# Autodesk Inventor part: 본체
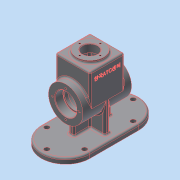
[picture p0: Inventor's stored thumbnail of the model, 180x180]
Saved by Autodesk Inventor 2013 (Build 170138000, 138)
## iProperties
Created: 2019-01
Part Number: 본체
Material: 알루미늄 6061
Document SubType Name: Modeling
Designer: mduedu
Density: 2.71 g/cm^3
Mass: 1057.72 g
Surface Area: 916.19 cm^2
Volume: 390.304 cm^3
Author: mduedu
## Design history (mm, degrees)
sketch "스케치1"
  geometry: C1 r 32 at (0, 0); 1 further point
  constraints: 1 centre point, 1 coincident
  dimensions: "d0" = 64 diameter of C1
extrude "돌출1" new body sketch "스케치1" stored distance "d1" = 90; taper "d2" = 0 deg
sketch "스케치2"
  geometry: L1 (0, 32)-(60, 32); L2 (60, 32)-(60, -32); L3 (60, -32)-(0, -32); L4 (0, -32)-(0, 32); C1 r 32 at (0, 0) reference; 2 further points
  constraints: 8 end point, 2 parallel, 1 coincident, 1 horizontal, 1 midpoint, 1 perpendicular, 1 tangent
  dimensions: "d5" = 60 distance between parallel lines of L4 L2
extrude "돌출2" join sketch "스케치2" stored distance "d7" = 64; taper "d8" = 0 deg
sketch "스케치3"
  geometry: C1 r 25 at (32, 32); 1 further point
  constraints: 1 centre point, 1 coincident
  dimensions: "d9" = 50 diameter of C1
extrude "돌출3" join sketch "스케치3" distance "d10" = 5; taper "d11" = 0 deg
sketch "스케치4"
  geometry: L1 (50, 25)-(0, 25); L2 (0, 25)-(0, -25); L3 (0, -25)-(50, -25); L4 (50, -25)-(50, 25); L5 (65, -25)-(65, 25) reference; A1 r 25 centre (0, 0) between (0, 25) and (0, -25); A2 r 25 centre (0, 0) between (0, -25) and (0, 25); 2 further points
  constraints: 8 end point, 4 point on circle, 2 centre point, 2 coincident, 2 parallel, 1 horizontal, 1 midpoint, 1 perpendicular, 1 tangent
  dimensions: "d12" = 50 diameter of A1; "d13" = 15 distance between parallel lines of L4 L5
extrude "돌출4" cut sketch "스케치4" stored distance "d14" = 48; taper "d15" = 0 deg
sketch "스케치5"
  geometry: C1 r 20 at (0, 0); 1 further point
  constraints: 1 centre point, 1 coincident
  dimensions: "d16" = 40 diameter of C1
extrude "돌출5" cut sketch "스케치5" distance "d17" = 15; taper "d18" = 0 deg
sketch "스케치6"
  geometry: C1 r 17 at (0, 0); 1 further point
  constraints: 1 centre point, 1 coincident
  dimensions: "d19" = 34 diameter of C1
extrude "돌출6" cut sketch "스케치6" stored distance "d20" = 15; taper "d21" = 0 deg
fillet "모깎기1" dims "d22" = 0.3
fillet "모깎기2" dims "d23" = 3
fillet "모깎기3" dims "d24" = 3
fillet "모깎기4" dims "d25" = 3
fillet "모깎기5" dims "d26" = 3
fillet "모깎기6" dims "d27" = 3
sketch "스케치7"
  geometry: C1 r 14 at (0, 0); 1 further point
  constraints: 1 centre point, 1 coincident
  dimensions: "d28" = 28 diameter of C1
extrude "돌출7" cut sketch "스케치7" stored distance "d29" = 15; taper "d30" = 0 deg
chamfer "모따기1" distance "d31" = 1; stored, may be unused: second distance "d32" = 2, angle "d33" = 45 deg
chamfer "모따기2" distance "d34" = 1; stored, may be unused: second distance "d35" = 2, angle "d36" = 45 deg
node "작업 평면1"
sketch "스케치8"
  geometry: L1 (45, 45)-(-45, 45); L2 (-45, 45)-(-45, -45); L3 (-45, -45)-(45, -45); L4 (45, -45)-(45, 45); L5 (45, 45)-(-45, -45); L6 (-45, 45)-(45, -45); A1 r 45 centre (45, 0) between (45, -45) and (45, 45); A2 r 45 centre (-45, 0) between (-45, 45) and (-45, -45); A3 r 45 centre (45, 0) between (0, 0) and (45, -45); A4 r 45 centre (45, 0) between (0, 0) and (0, 0); A5 r 45 centre (45, 0) between (45, 45) and (0, 0); A6 r 45 centre (-45, 0) between (0, 0) and (-45, 45); A7 r 45 centre (-45, 0) between (-45, -45) and (0, 0); 1 further point
  constraints: 14 point on circle, 12 end point, 7 centre point, 7 midpoint, 2 parallel, 1 horizontal, 1 perpendicular
  dimensions: "d99" = 90 distance between parallel lines of L1 L3; "d101" = 90 distance between parallel lines of L2 L4
extrude "돌출8" join sketch "스케치8" distance "d41" = 10; taper "d42" = 0 deg
sketch "스케치9"
  geometry: L1 (-35, 5)-(35, 5); L2 (35, 5)-(35, -5); L3 (35, -5)-(-35, -5); L4 (-35, -5)-(-35, 5); 3 further points
  constraints: 8 end point, 2 midpoint, 2 parallel, 1 horizontal, 1 horizontal alignment, 1 perpendicular, 1 vertical alignment
  dimensions: "d52" = 10 distance of L1.end L2.end; "d54" = 70 distance of L1.start L1.end
extrude "돌출9" join sketch "스케치9" stored distance "d50" = 10; taper "d51" = 0 deg
sketch "스케치10"
  geometry: L1 (0, -25)-(47, -25) reference; L2 (50, -22)-(50, -14) reference; L3 (50, -14)-(64, -14) reference; L4 (64, -14)-(65, -15) reference; L5 (65, -15)-(65, -25) reference; L6 (65, -25)-(63, -25) reference; L7 (60, -28)-(60, -29) reference; L8 (57, -32)-(0, -32) reference; L9 (-31.607, -5)-(-55, -5) reference; L10 (-55, -5)-(-55, -45) reference; L11 (-65, -45)-(-65, 45) reference; L12 (-55, 45)-(-55, 5) reference; L13 (-55, 5)-(-31.607, 5) reference; L14 (0, 32)-(57, 32) reference; L15 (60, 29)-(60, 28) reference; L16 (63, 25)-(65, 25) reference; L17 (65, 25)-(65, 15) reference; L18 (65, 15)-(64, 14) reference; L19 (64, 14)-(50, 14) reference; L20 (50, 14)-(50, 22) reference; L21 (47, 25)-(0, 25) reference; L22 (-55, -45)-(-65, -45) reference; L23 (-65, 45)-(-55, 45) reference; L24 (0, 32)-(-55, 32); A1 r 25 centre (0, 0) between (0, 25) and (0, -25) reference; A2 r 3 centre (47, -22) between (47, -25) and (50, -22) reference; A3 r 3 centre (63, -28) between (63, -25) and (60, -28) reference; A4 r 3 centre (57, -29) between (57, -32) and (60, -29) reference; A5 r 32 centre (0, 0) between (-31.607, -5) and (0, -32) reference; A6 r 32 centre (0, 0) between (0, 32) and (-31.607, 5) reference; A7 r 3 centre (57, 29) between (60, 29) and (57, 32) reference; A8 r 3 centre (63, 28) between (60, 28) and (63, 25) reference; A9 r 3 centre (47, 22) between (50, 22) and (47, 25) reference
  constraints: 2 end point, 1 perpendicular, 1 point on line, 1 tangent
feature "리브1" sketch "스케치10" dims "d57" = 1, "d58" = 10, "d59" = 0, "d60" = 0, "d61" = 1, "d62" = 1
fillet "모깎기7" dims "d63" = 3
fillet "모깎기11" dims "d102" = 3
fillet "모깎기8" dims "d64" = 3
sketch "스케치11"
  geometry: L1 (8, -29)-(8, -8) reference; L2 (-8, -8)-(-8, -29) reference; L3 (-32, -8)-(-8, -8) reference; L4 (-38, 2)-(-38, -2) reference; L5 (-8, 8)-(-32, 8) reference; L6 (-8, 29)-(-8, 8) reference; L7 (8, 8)-(8, 29) reference; L8 (32, 8)-(8, 8) reference; L9 (38, -2)-(38, 2) reference; L10 (8, -8)-(32, -8) reference; L11 (-2, -35)-(2, -35) reference; L12 (2, 35)-(-2, 35) reference; L13 (-45, -45)-(45, -45) reference; L14 (45, 45)-(-45, 45) reference; L15 (-45, -35)-(45, -35); L16 (45, 35)-(-45, 35); A1 r 6 centre (-32, -2) between (-38, -2) and (-32, -8) reference; A2 r 6 centre (-32, 2) between (-32, 8) and (-38, 2) reference; A3 r 6 centre (32, 2) between (38, 2) and (32, 8) reference; A4 r 6 centre (32, -2) between (32, -8) and (38, -2) reference; A5 r 6 centre (2, -29) between (2, -35) and (8, -29) reference; A6 r 6 centre (-2, -29) between (-8, -29) and (-2, -35) reference; A7 r 6 centre (-2, 29) between (-2, 35) and (-8, 29) reference; A8 r 6 centre (2, 29) between (8, 29) and (2, 35) reference; A9 r 45 centre (-45, 0) between (-45, 45) and (-45, -45) reference; A10 r 45 centre (45, 0) between (45, -45) and (45, 45) reference; A11 r 35 centre (-45, 0) between (-45, 35) and (-45, -35); A12 r 35 centre (45, 0) between (45, -35) and (45, 35); 7 further points
  constraints: 6 point on circle, 4 coincident, 4 end point, 2 centre point, 3 other
  dimensions: "d103" = 10 distance between parallel lines of L16 L14
hole "구멍1" sketch "스케치11" at (-45, 35), (-80, 0), (-45, -35), (45, -35), (80, 0), (45, 35) diameter "d66" = 9; stored, may be unused: countersink angle "d70" = 90 deg, drill point angle "d72" = 118 deg; dims "d67" = 6, "d68" = 4, "d69" = 2, "d71" = 8
fillet "모깎기10" dims "d73" = 3
sketch "스케치12"
  geometry: L1 (-3, 57)-(-3, 19.596) reference; 2 further points
  constraints: 1 other
  dimensions: "d74" = 32 distance from line of point (29, 45) L1; "d75" = 45 distance of point (29, 45) point (29, 0)
feature "엠보싱1" sketch "스케치12" dims "d12" = 50, "d13" = 15, "d76" = 0.5, "d77" = 0
sketch "스케치13"
  geometry: 4 further points
  constraints: 4 other
hole "구멍2" sketch "스케치13" at (-25, 0), (0, -25), (25, 0), (0, 25) diameter "d78" = 3.242; stored, may be unused: countersink angle "d82" = 90 deg, drill point angle "d84" = 120 deg; dims "d79" = 7, "d80" = 4, "d81" = 2, "d83" = 9
sketch "스케치14"
  geometry: 4 further points
  constraints: 4 other
hole "구멍3" sketch "스케치14" at (-25, 0), (0, -25), (25, 0), (0, 25) diameter "d85" = 3.242; stored, may be unused: countersink angle "d89" = 90 deg, drill point angle "d91" = 120 deg; dims "d86" = 7, "d87" = 4, "d88" = 2, "d90" = 9
sketch "스케치15"
  geometry: 4 further points
  constraints: 4 other
hole "구멍4" sketch "스케치15" at (0, -19), (19, 0), (0, 19), (-19, 0) diameter "d92" = 3.242; stored, may be unused: countersink angle "d96" = 90 deg, drill point angle "d98" = 120 deg; dims "d93" = 8, "d94" = 4, "d95" = 2, "d97" = 10
node "솔리드1"
mirror "대칭1"
mirror "대칭2"
node "투영된 루프1"
node "투영된 루프2"
node "절단 모서리 투영1"
node "절단 모서리 투영2"
other parameters: "d37" = -65
